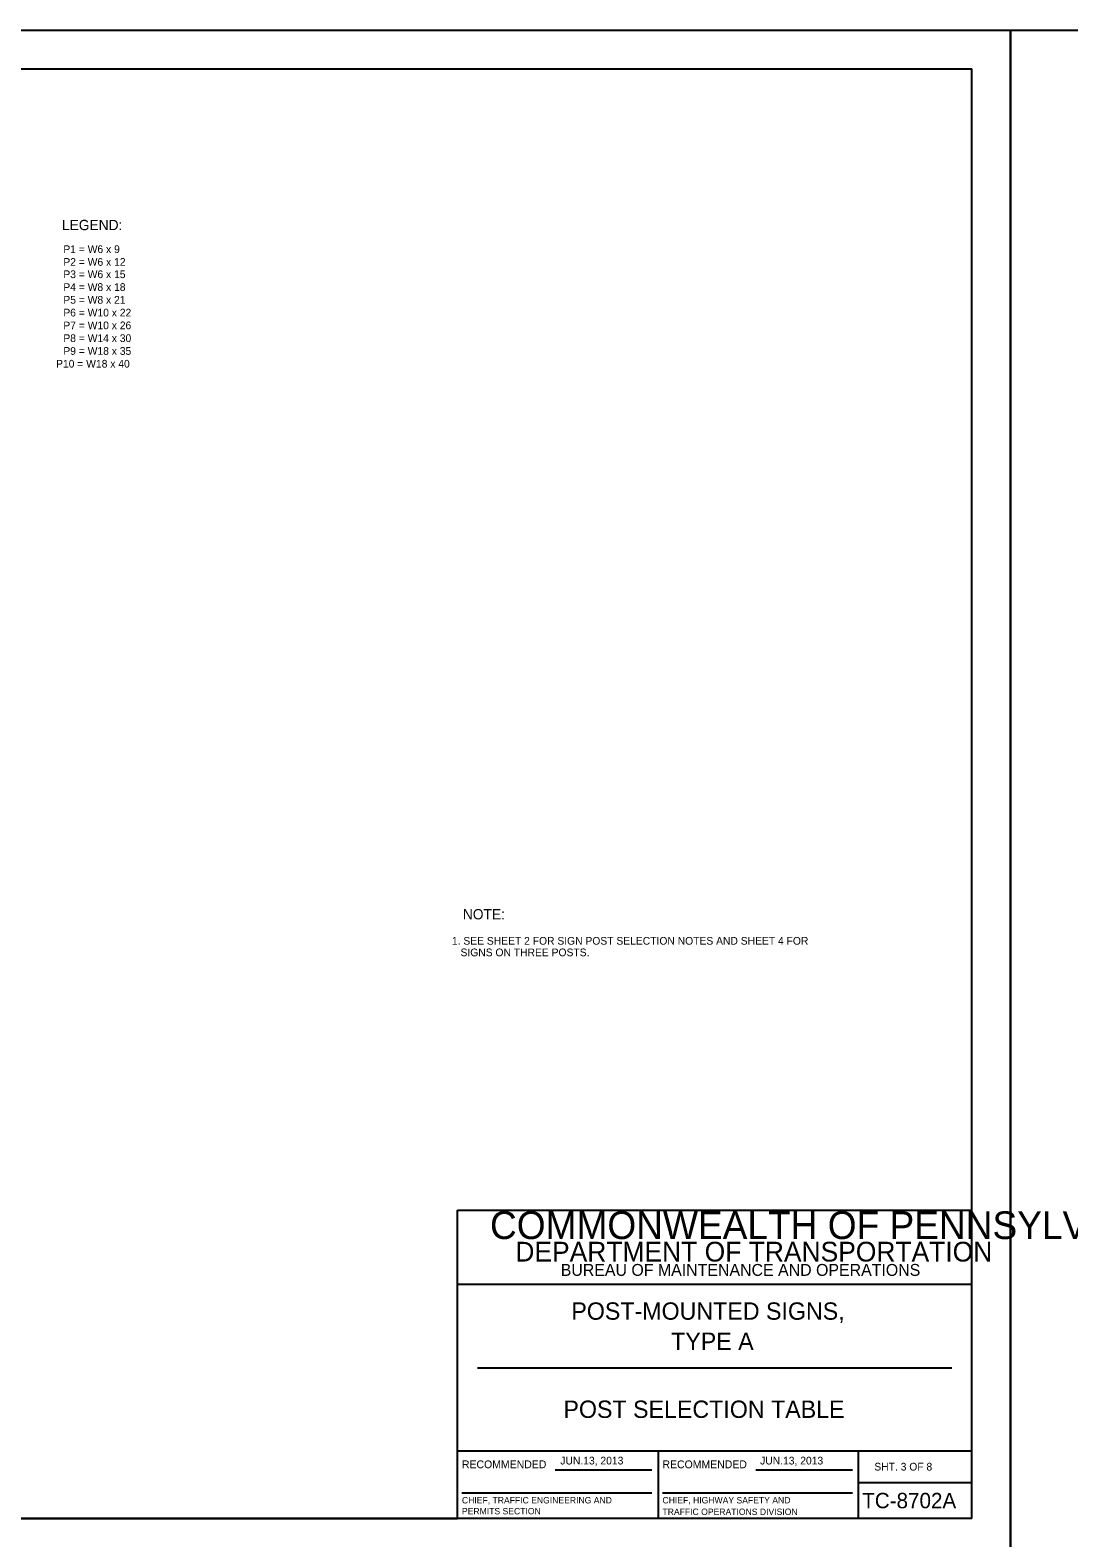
# Model space of a CAD drawing. Extents: x 637580 to 641008, y 294594 to 295782.
# Drawn here: x 639722 to 640126, y 295195 to 295782 of the extents above; entities that cross this region are included whole.
import ezdxf

# ---------------------------------------------------------------- set-up
doc = ezdxf.new("R2010")
doc.units = 0
for name, color, linetype in [('1', 7, 'Continuous'), ('2', 7, 'Continuous'), ('PLT-BNDY', 7, 'Continuous')]:
    doc.layers.add(name, color=color, linetype=linetype)

msp = doc.modelspace()

# ---------------------------------------------------------------- linework, layer by layer
at = {"layer": '1'}
for p, q in [((639302.31, 295766.63), (640088.31, 295766.63)), ((640088.31, 295202.63), (640088.31, 295766.63)), ((639888.31, 295202.63), (639888.31, 295322.63)), ((639888.31, 295322.63), (640088.31, 295322.63)), ((640088.31, 295293.63), (639888.31, 295293.63)), ((639896.06, 295261.31), (640080.56, 295261.31)), ((639888.31, 295229), (640088.31, 295229)), ((639966.31, 295229), (639966.31, 295202.63)), ((640044.19, 295202.63), (640044.19, 295229)), ((639926.24, 295221.57), (639963.87, 295221.57)), ((640004.24, 295221.57), (640041.87, 295221.57)), ((640044.19, 295216.63), (640088.31, 295216.63)), ((639889.99, 295212.68), (639963.87, 295212.68)), ((639967.99, 295212.68), (640041.87, 295212.68)), ((640088.31, 295202.63), (639302.31, 295202.63)), ((639302.31, 295202.63), (639888.31, 295202.63))]:
    msp.add_line(p, q, dxfattribs=at)
at = {"layer": 'PLT-BNDY'}
for points in [[(639262.31, 295781.63), (640103.31, 295781.63), (640103.31, 295187.63), (639262.31, 295187.63)], [(640103.31, 295781.63), (640944.31, 295781.63), (640944.31, 295187.63), (640103.31, 295187.63)]]:
    msp.add_lwpolyline(points, close=True, dxfattribs=at)

# ---------------------------------------------------------------- texts
at = {"layer": '1'}
for s, height, p in [('LEGEND:', 4.003, (639734.41, 295703.83)), ('P1 = W6 x 9', 3, (639734.94, 295694.92)), ('P2 = W6 x 12', 3, (639734.94, 295689.95)), ('P3 = W6 x 15', 3, (639734.94, 295685.17)), ('P4 = W8 x 18', 3, (639734.94, 295680.19)), ('P5 = W8 x 21', 3, (639734.94, 295675.22)), ('P6 = W10 x 22', 3, (639734.94, 295670.25)), ('P7 = W10 x 26', 3, (639734.94, 295665.28)), ('P8 = W14 x 30', 3, (639734.94, 295660.3)), ('P9 = W18 x 35', 3, (639734.94, 295655.33)), ('P10 = W18 x 40', 3, (639732.12, 295650.36)), (' 1. SEE SHEET 2 FOR SIGN POST SELECTION NOTES AND SHEET 4 FOR', 3, (639884.97, 295425.87)), ('    SIGNS ON THREE POSTS.', 3, (639884.97, 295421.37)), ('COMMONWEALTH OF PENNSYLVANIA', 10.7828, (639900.9, 295311.36)), ('DEPARTMENT OF TRANSPORTATION', 7.6837, (639910.76, 295302.61)), ('BUREAU OF MAINTENANCE AND OPERATIONS', 4.6253, (639928.41, 295297.04)), ('POST-MOUNTED SIGNS,', 6.75, (639932.54, 295279.97)), ('TYPE A', 6.75, (639971.35, 295268.22)), ('POST SELECTION TABLE', 6.75, (639929.47, 295241.78)), ('RECOMMENDED', 3.048, (639889.99, 295222.2)), ('RECOMMENDED', 3.048, (639967.99, 295222.2)), ('SHT. 3 OF 8', 3, (640050.4, 295221.31)), ('CHIEF, TRAFFIC ENGINEERING AND', 2.5, (639889.99, 295208.51)), ('CHIEF, HIGHWAY SAFETY AND', 2.5, (639967.99, 295208.51)), ('TC-8702A', 6, (640045.68, 295206.63)), ('PERMITS SECTION', 2.5, (639889.99, 295204.26)), ('TRAFFIC OPERATIONS DIVISION', 2.5, (639967.99, 295204.01))]:
    msp.add_text(s, height=height, dxfattribs=at).set_placement(p)
at = {"layer": '2'}
for s, height, p in [('NOTE:', 4.003, (639890.35, 295435.71)), ('JUN.13, 2013', 3, (639928.25, 295223.67)), ('JUN.13, 2013', 3, (640005.97, 295223.67))]:
    msp.add_text(s, height=height, dxfattribs=at).set_placement(p)

doc.saveas('drawing.dxf')
